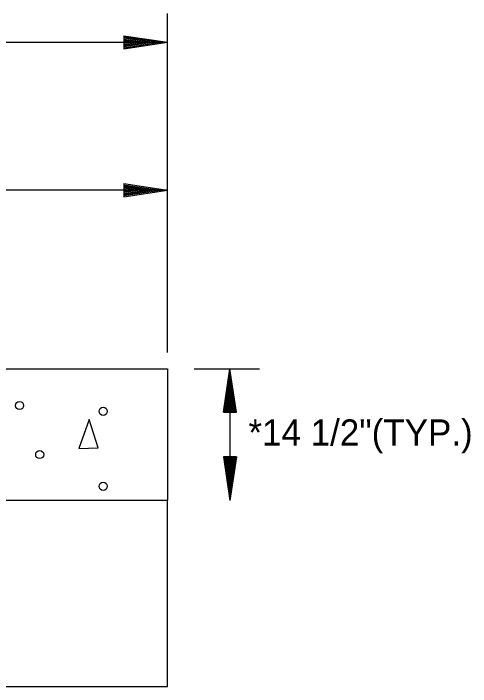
# Model space of a CAD drawing. Extents: x 3287 to 1767681, y -265 to 581440.
# Drawn here: x 3501.94 to 3522.92, y -55.33 to -24.43 of the extents above; entities that cross this region are included whole.
import ezdxf

# ---------------------------------------------------------------- set-up
doc = ezdxf.new("R2010")
doc.units = 0
doc.layers.add('Default', color=7, linetype='Continuous')

msp = doc.modelspace()

# ---------------------------------------------------------------- linework, layer by layer
at = {"layer": 'Default'}
for p, q in [((3509.005, -39.994), (3509.005, -24.434)), ((3507.008, -25.457), (3509.008, -25.757)), ((3507.008, -25.457), (3507.008, -26.057)), ((3507.008, -25.507), (3508.673, -25.757)), ((3507.008, -25.557), (3508.328, -25.757)), ((3507.008, -25.607), (3507.998, -25.757)), ((3426.51, -25.756), (3509.005, -25.756)), ((3507.008, -25.657), (3507.658, -25.757)), ((3507.008, -25.707), (3507.323, -25.757)), ((3507.008, -26.057), (3509.008, -25.757)), ((3507.008, -25.852), (3507.658, -25.757)), ((3507.008, -25.957), (3508.328, -25.757)), ((3507.008, -26.007), (3508.673, -25.757)), ((3507.008, -25.907), (3507.998, -25.757)), ((3507.008, -25.802), (3507.323, -25.757)), ((3509.005, -39.994), (3509.005, -31.468)), ((3509.005, -39.994), (3509.005, -31.468)), ((3507.005, -32.246), (3509.005, -32.546)), ((3507.005, -32.246), (3507.005, -32.846)), ((3507.005, -32.296), (3508.67, -32.546)), ((3507.005, -32.346), (3508.325, -32.546)), ((3507.005, -32.396), (3507.995, -32.546)), ((3507.005, -32.446), (3507.655, -32.546)), ((3509.005, -32.546), (3494.006, -32.546)), ((3507.005, -32.496), (3507.32, -32.546)), ((3507.005, -32.846), (3509.005, -32.546)), ((3507.005, -32.641), (3507.655, -32.546)), ((3507.005, -32.746), (3508.325, -32.546)), ((3507.005, -32.796), (3508.67, -32.546)), ((3507.005, -32.696), (3507.995, -32.546)), ((3507.005, -32.591), (3507.32, -32.546)), ((3326.516, -40.744), (3509.005, -40.744)), ((3509.005, -40.744), (3509.005, -46.785)), ((3510.241, -40.744), (3513.229, -40.744)), ((3511.577, -42.741), (3511.877, -40.742)), ((3512.177, -42.741), (3511.877, -40.742)), ((3511.879, -40.744), (3511.879, -46.785)), ((3511.627, -42.741), (3511.877, -41.071)), ((3512.127, -42.741), (3511.877, -41.071)), ((3511.682, -42.741), (3511.877, -41.416)), ((3512.077, -42.741), (3511.877, -41.416)), ((3511.732, -42.741), (3511.877, -41.751)), ((3512.027, -42.741), (3511.877, -41.751)), ((3511.782, -42.741), (3511.877, -42.091)), ((3511.977, -42.741), (3511.877, -42.091)), ((3511.832, -42.741), (3511.877, -42.421)), ((3511.927, -42.741), (3511.877, -42.421)), ((3511.577, -42.741), (3512.177, -42.741)), ((3511.577, -44.786), (3511.877, -46.786)), ((3512.177, -44.786), (3511.577, -44.786)), ((3511.627, -44.786), (3511.877, -46.451)), ((3511.682, -44.786), (3511.877, -46.106)), ((3511.732, -44.786), (3511.877, -45.776)), ((3511.782, -44.786), (3511.877, -45.436)), ((3511.832, -44.786), (3511.877, -45.101)), ((3512.177, -44.786), (3511.877, -46.786)), ((3511.977, -44.786), (3511.877, -45.436)), ((3512.077, -44.786), (3511.877, -46.106)), ((3512.127, -44.786), (3511.877, -46.451)), ((3512.027, -44.786), (3511.877, -45.776)), ((3511.927, -44.786), (3511.877, -45.101)), ((3494.006, -46.785), (3509.005, -46.785)), ((3509.005, -55.335), (3509.005, -46.785)), ((3494.006, -55.335), (3509.005, -55.335))]:
    msp.add_line(p, q, dxfattribs=at)
msp.add_lwpolyline([(3505.423, -43.076), (3504.943, -44.406), (3505.823, -44.371), (3505.423, -43.076)], dxfattribs=at)
for centre in [(3502.223, -42.432), (3506.061, -42.697), (3503.149, -44.684), (3506.061, -46.14)]:
    msp.add_circle(centre, 0.187, dxfattribs=at)

# ---------------------------------------------------------------- texts
msp.add_text('*14 1/2"(TYP.)', height=1.2, dxfattribs=at).set_placement((3512.727, -44.271))

doc.saveas('drawing.dxf')
